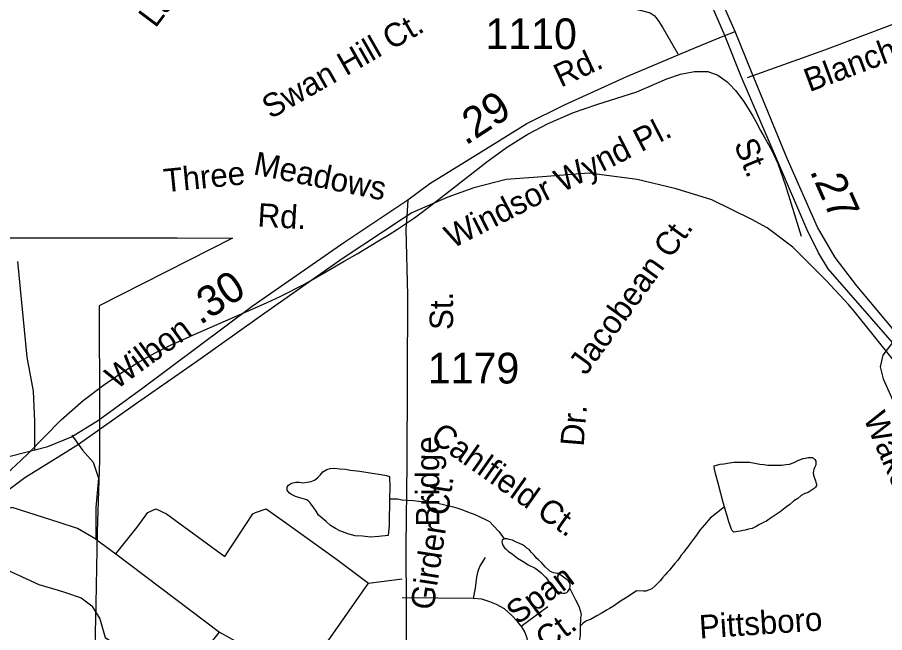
# Model space of a CAD drawing. Extents: x 2001466 to 2224147, y 644118 to 847247.
# Drawn here: x 2055654 to 2059179, y 671798 to 674300 of the extents above; entities that cross this region are included whole.
import ezdxf

# ---------------------------------------------------------------- set-up
doc = ezdxf.new("R2010")
doc.units = 0
for name, color, linetype in [('Exist Boundary Political City Limit New', 7, 'Continuous'), ('Exist Hydrographic Misc Water Feature', 7, 'Continuous'), ('Exist Railroad Mainline', 7, 'Continuous'), ('Exist Road Non-System Type 51', 7, 'Continuous'), ('Exist Road Non-System Type 51 Label', 7, 'Continuous'), ('Exist Road Primary NC Divided Attributed', 7, 'Continuous'), ('Exist Road Primary NC Label', 7, 'Continuous'), ('Exist Road Primary NC Service Mileage Hundredths English Label', 7, 'Continuous'), ('Exist Road Secondary Mileage Hundredths English Label', 7, 'Continuous'), ('Exist Road Secondary Type 51 Attributed', 7, 'Continuous'), ('Exist Road Secondary Type 51 Label', 7, 'Continuous'), ('Exist Road Secondary Type 51 Number Label', 7, 'Continuous'), ('Map Preparation Boundary City Limit Buffer Line', 7, 'Continuous')]:
    doc.layers.add(name, color=color, linetype=linetype)

msp = doc.modelspace()

# ---------------------------------------------------------------- linework, layer by layer
at = {"layer": 'Exist Boundary Political City Limit New'}
msp.add_lwpolyline([(2055624, 673403.6), (2055688.9, 673403.6), (2055823.9, 673403.5), (2055896.9, 673403.4), (2055968.9, 673403.4), (2056033.8, 673403.4), (2056108.6, 673403.3), (2056188.5, 673403.2), (2056303.8, 673403.2), (2056528.9, 673402.2), (2055987, 673126.9), (2055987.4, 672699.7), (2055987.5, 672626.9), (2055987.5, 672561.8), (2055987.6, 672500), (2055978.4, 672208.1), (2055972.6, 671915.2), (2055972.6, 671912.9), (2055959.8, 671338.6)], dxfattribs=at)
at = {"layer": 'Exist Hydrographic Misc Water Feature'}
for p, q in [((2057722.5, 673821.3), (2057728.6, 673824.6)), ((2057562.5, 673713), (2057577.3, 673723.6))]:
    msp.add_line(p, q, dxfattribs=at)
for points in [[(2058253.1, 674031.7), (2058293.5, 674049.2), (2058349.5, 674068.7), (2058406.7, 674080.3), (2058460.4, 674079), (2058501.5, 674064.7), (2058519.7, 674051.8)], [(2058253.1, 674031.7), (2058293.5, 674049.2), (2058349.5, 674068.7), (2058406.7, 674080.3), (2058460.4, 674079), (2058501.5, 674064.7), (2058519.7, 674051.8)], [(2057914.4, 673912.9), (2058008.5, 673945.7), (2058171.5, 673996.7), (2058253.1, 674031.7)], [(2057914.4, 673912.9), (2058008.5, 673945.7), (2058171.5, 673996.7), (2058253.1, 674031.7)], [(2058519.7, 674051.8), (2058538.6, 674038.3), (2058550.3, 674026.4)], [(2058519.7, 674051.8), (2058538.6, 674038.3), (2058550.3, 674026.4)], [(2058550.3, 674026.4), (2058573.4, 674002.1), (2058606.2, 673957.1)], [(2058550.3, 674026.4), (2058573.4, 674002.1), (2058606.2, 673957.1)], [(2058606.2, 673957.1), (2058643.6, 673897.5), (2058655, 673876.3)], [(2058606.2, 673957.1), (2058643.6, 673897.5), (2058655, 673876.3)], [(2057728.6, 673824.6), (2057811.5, 673868.1), (2057914.4, 673912.9)], [(2057728.6, 673824.6), (2057811.5, 673868.1), (2057914.4, 673912.9)], [(2058655, 673876.3), (2058674.3, 673840.2), (2058689.1, 673814)], [(2058655, 673876.3), (2058674.3, 673840.2), (2058689.1, 673814)], [(2057577.3, 673723.6), (2057642.5, 673770.2), (2057722.5, 673821.3)], [(2057577.3, 673723.6), (2057642.5, 673770.2), (2057722.5, 673821.3)], [(2058689.1, 673814), (2058718.6, 673761.2), (2058744.4, 673705), (2058775.6, 673616.3), (2058839.2, 673409.8)], [(2057164.9, 673417.6), (2057198.4, 673438.5), (2057267.5, 673485.2), (2057334.5, 673535.5), (2057562.5, 673713)], [(2057164.9, 673417.6), (2057198.4, 673438.5), (2057267.5, 673485.2), (2057334.5, 673535.5), (2057562.5, 673713)], [(2056982.8, 673308.3), (2057034.5, 673338.5), (2057121.5, 673390.6), (2057164.9, 673417.6)], [(2056982.8, 673308.3), (2057034.5, 673338.5), (2057121.5, 673390.6), (2057164.9, 673417.6)], [(2056820.4, 673215.6), (2056933.4, 673279.5), (2056982.8, 673308.3)], [(2056820.4, 673215.6), (2056933.4, 673279.5), (2056982.8, 673308.3)], [(2056669.1, 673140.7), (2056722.4, 673165.5), (2056820.4, 673215.6)], [(2056669.1, 673140.7), (2056722.4, 673165.5), (2056820.4, 673215.6)], [(2056310.3, 672982.5), (2056369.5, 673009.5), (2056630.6, 673122.7), (2056669.1, 673140.7)], [(2056310.3, 672982.5), (2056369.5, 673009.5), (2056630.6, 673122.7), (2056669.1, 673140.7)], [(2056078.6, 672855.5), (2056146.4, 672898.3), (2056213.5, 672935.6), (2056287.5, 672972.2), (2056310.3, 672982.5)], [(2056078.6, 672855.5), (2056146.4, 672898.3), (2056213.5, 672935.6), (2056287.5, 672972.2), (2056310.3, 672982.5)], [(2055921.5, 672741.5), (2056004.5, 672804.2), (2056078.6, 672855.5)], [(2055921.5, 672741.5), (2056004.5, 672804.2), (2056078.6, 672855.5)], [(2055669.1, 672499.2), (2055696.6, 672524.9), (2055831.5, 672664), (2055921.5, 672741.5)], [(2055669.1, 672499.2), (2055696.6, 672524.9), (2055831.5, 672664), (2055921.5, 672741.5)], [(2058528.1, 672309.2), (2058522, 672327.2), (2058503.9, 672401.2), (2058491.8, 672445.2), (2058487.7, 672463.1), (2058485.9, 672477.1), (2058509.9, 672483.2), (2058525.9, 672485.2), (2058547.8, 672489.2), (2058567.9, 672491.3), (2058587.8, 672491.3), (2058605.6, 672491.4), (2058629.6, 672491.4), (2058651.8, 672487.4), (2058671.9, 672483.5), (2058687.9, 672481.5), (2058703.8, 672479.5), (2058719.6, 672479.5), (2058741.8, 672479.6), (2058761.7, 672479.6), (2058777.7, 672481.7), (2058791.6, 672483.7), (2058811.7, 672489.7), (2058825.6, 672497.7), (2058847.6, 672505.8), (2058857.6, 672507.8), (2058867.7, 672509.8), (2058877.7, 672509.9), (2058883.7, 672509.9), (2058889.6, 672507.9), (2058895.8, 672501.9), (2058899.7, 672495.9), (2058899.7, 672483.9), (2058897.6, 672475.9), (2058893.7, 672467.8), (2058891.7, 672461.8), (2058889.8, 672455.9), (2058887.8, 672447.9), (2058889.8, 672437.9), (2058891.9, 672429.9), (2058897.8, 672415.9), (2058899.9, 672409.9), (2058901.7, 672401.9), (2058901.7, 672395.9), (2058898, 672389.9), (2058891.9, 672383.9), (2058880, 672375.9), (2058867.9, 672367.9), (2058853.9, 672363.8), (2058840, 672355.8), (2058825.9, 672343.8), (2058809.9, 672333.7), (2058794.1, 672319.7), (2058780.1, 672309.7), (2058768, 672299.7), (2058754.1, 672289.7), (2058734, 672275.6), (2058710.2, 672259.6), (2058698.1, 672251.6), (2058686.2, 672245.6), (2058670.2, 672237.5), (2058656.3, 672229.5), (2058640.3, 672221.5), (2058626.1, 672219.4), (2058612.4, 672215.4), (2058602.3, 672213.4), (2058592.3, 672211.4), (2058582.3, 672209.4), (2058566.3, 672207.3), (2058558.3, 672215.3), (2058546.2, 672249.3), (2058528.1, 672309.2)], [(2055558.1, 672412.4), (2055628.7, 672461.7), (2055669.1, 672499.2)], [(2055558.1, 672412.4), (2055628.7, 672461.7), (2055669.1, 672499.2)], [(2057166.4, 672342.7), (2057166.4, 672324.7), (2057164.5, 672258.7), (2057164.5, 672232.7), (2057162.5, 672208.7), (2057160.6, 672192.7), (2057122.5, 672188.7), (2057088.7, 672186.6), (2057056.7, 672190.5), (2057026.5, 672192.5), (2056996.6, 672200.4), (2056964.6, 672212.4), (2056946.6, 672222.3), (2056926.7, 672234.2), (2056908.6, 672250.3), (2056892.4, 672264.2), (2056878.5, 672276.2), (2056868.4, 672292.1), (2056858.4, 672306.2), (2056848.5, 672320.2), (2056844.4, 672326.1), (2056840.5, 672330.1), (2056830.5, 672338.1), (2056802.4, 672346), (2056784.4, 672352), (2056768.4, 672359.9), (2056760.4, 672365.9), (2056754.4, 672371.9), (2056750.3, 672377.9), (2056750.3, 672389.9), (2056756.3, 672397.9), (2056768.4, 672406), (2056786.4, 672410), (2056800.1, 672410), (2056814.3, 672408), (2056832.1, 672410.1), (2056848.1, 672412.1), (2056862.3, 672418.1), (2056874.2, 672428.1), (2056884.2, 672438.1), (2056896.1, 672452.2), (2056912.1, 672462.2), (2056926, 672466.2), (2056942, 672466.3), (2056964, 672464.3), (2056988.2, 672462.3), (2057008.1, 672458.4), (2057046, 672454.5), (2057096.2, 672446.6), (2057132.1, 672440.6), (2057154.3, 672436.6), (2057166.2, 672432.7), (2057166.2, 672428.7), (2057168.2, 672390.7), (2057166.4, 672342.7)], [(2057166.4, 672342.7), (2057198.4, 672342.8), (2057218.2, 672338.8), (2057238.3, 672336.8), (2057262.3, 672334.9), (2057286.3, 672332.9), (2057316.3, 672331), (2057336.4, 672327), (2057362.4, 672325.1), (2057386.4, 672319.1), (2057420.2, 672311.1), (2057440.3, 672305.2), (2057460.4, 672299.3), (2057490.3, 672287.3), (2057510.2, 672279.4), (2057534.2, 672269.4), (2057554.5, 672259.5), (2057572.4, 672249.5), (2057588.4, 672233.5)], [(2058528.1, 672309.2), (2058470.1, 672263.1), (2058446.1, 672237.1), (2058428.3, 672215.1), (2058414.3, 672195), (2058400.4, 672177), (2058388.5, 672161), (2058378.4, 672147), (2058370.4, 672137), (2058362.4, 672125), (2058352.4, 672112.9), (2058344.6, 672102.9), (2058338.6, 672092.9), (2058326.6, 672078.9), (2058314.5, 672064.9), (2058304.6, 672052.9), (2058294.8, 672042.9), (2058286.8, 672032.9), (2058276.7, 672020.9), (2058266.7, 672008.8), (2058256.6, 671998.8), (2058244.7, 671986.8), (2058232.8, 671976.7), (2058218.9, 671970.7), (2058208.9, 671966.7), (2058198.8, 671966.6), (2058170.7, 671968.6)], [(2057588.4, 672233.5), (2057612.4, 672207.5), (2057633.1, 672179.5)], [(2057633.1, 672179.5), (2057624.7, 672173.6), (2057622.6, 672167.6), (2057624.7, 672161.6), (2057626.5, 672153.6), (2057634.5, 672143.6), (2057640.7, 672137.6), (2057648.6, 672129.7), (2057666.5, 672117.7), (2057686.6, 672101.7), (2057702.8, 672091.7), (2057716.7, 672083.8), (2057730.7, 672073.8), (2057758.8, 672059.8), (2057768.6, 672053.8), (2057782.8, 672041.9), (2057792.8, 672031.9), (2057800.8, 672024), (2057808.8, 672014), (2057812.9, 672008), (2057818.8, 672000), (2057828.9, 671986), (2057832.8, 671978), (2057836.9, 671974), (2057844.9, 671968), (2057852.9, 671964), (2057860.9, 671960), (2057870.7, 671958.1), (2057878.7, 671958.1), (2057886.7, 671962.1), (2057890.8, 671966.1), (2057896.8, 671974.2), (2057898.8, 671978.2)], [(2057898.8, 671978.2), (2057900.9, 671986.2), (2057900.9, 671998.2), (2057892.9, 672010.1), (2057884.9, 672016.1), (2057868.7, 672028.1), (2057858.6, 672034.1), (2057850.6, 672038.1), (2057842.6, 672040.1), (2057832.6, 672042), (2057826.6, 672044), (2057818.6, 672048), (2057814.7, 672051.9), (2057798.7, 672065.9), (2057790.7, 672075.9), (2057784.6, 672083.9), (2057772.7, 672093.8), (2057764.7, 672099.8), (2057754.7, 672113.8), (2057742.6, 672125.9), (2057734.6, 672135.8), (2057724.5, 672141.8), (2057718.6, 672147.8), (2057706.5, 672155.7), (2057692.5, 672161.7), (2057678.6, 672167.7), (2057666.5, 672173.6), (2057652.5, 672177.6), (2057644.5, 672179.6), (2057633.1, 672179.5)], [(2057898.8, 671978.2), (2057910.7, 671956.1), (2057923, 671932.1), (2057931, 671916.2), (2057937, 671902.2), (2057940.8, 671888.2), (2057944.9, 671870.2), (2057943.1, 671860.2), (2057943.1, 671848.2), (2057941.1, 671830.2), (2057941.1, 671824.2)], [(2058170.7, 671968.6), (2058144.9, 671950.6), (2058118.8, 671934.6), (2058104.9, 671926.6), (2058077, 671906.5), (2058061, 671896.5), (2058051, 671890.4), (2058027, 671876.4), (2058009.1, 671866.4), (2057983.1, 671852.3), (2057967.1, 671846.3), (2057953.2, 671836.3), (2057941.1, 671824.2)], [(2057941.1, 671824.2), (2057941.1, 671818.2), (2057941.3, 671802.2), (2057941.3, 671786.2), (2057939.2, 671770.2), (2057939.2, 671758.2), (2057939.2, 671746.2), (2057937.4, 671732.2), (2057933.3, 671714.2), (2057929.4, 671692.2)]]:
    msp.add_lwpolyline(points, dxfattribs=at)
at = {"layer": 'Exist Railroad Mainline'}
for points in [[(2059031.5, 673131.8), (2058941.3, 673229.8), (2058805.2, 673365.8), (2058701.2, 673443.7), (2058639.3, 673477.8), (2058477.1, 673557.7), (2058332.2, 673602.5), (2058173.6, 673640.3), (2057977.2, 673666.8), (2057788.3, 673651.7), (2057641, 673640.3), (2057508.8, 673606.3), (2057403, 673568.5), (2057257.5, 673504.6), (2057218.2, 673479.1)], [(2057218.2, 673479.1), (2057137.5, 673426.7), (2056973.5, 673318.4), (2056636.3, 673081.1), (2056387, 672903.5), (2056137.7, 672729.7), (2055902.7, 672563.3), (2055892.2, 672555.8), (2055827.3, 672515.7), (2055684.4, 672427.4), (2055450.3, 672253.5), (2055321.8, 672170.4), (2055197.2, 672110), (2054951.7, 672019.3), (2054770.4, 671977.7), (2054593.3, 671966.4), (2054592.9, 671966.4), (2054219.7, 671991.7), (2054038.5, 672004), (2053746.7, 672011.7), (2053340.6, 672017.3), (2052916.7, 672031.1), (2052492.7, 672044.8), (2052327.8, 672061.8)], [(2059569.8, 672487.6), (2059215.5, 672905.9), (2059055.3, 673105.9), (2059031.5, 673131.8)]]:
    msp.add_lwpolyline(points, dxfattribs=at)
at = {"layer": 'Exist Road Non-System Type 51'}
for p, q in [((2055875.2, 672601.4), (2055902.7, 672563.3)), ((2055973.4, 672178.1), (2056054.4, 672118.6)), ((2056054.4, 672118.6), (2056475.6, 671799.9)), ((2057080.5, 671999.8), (2057218.1, 672016.5)), ((2057507.5, 671937.4), (2057218.1, 671939.8)), ((2057702.2, 671824.4), (2057810.4, 671903.9))]:
    msp.add_line(p, q, dxfattribs=at)
for points in [[(2057887.4, 674618.5), (2057919.3, 674566.6), (2057983.2, 674467.3), (2058008.5, 674430.8), (2058037.7, 674390.2), (2058055.3, 674369.8), (2058065.1, 674359.6), (2058090.8, 674345.1), (2058116.6, 674336.6), (2058152.6, 674335.8), (2058190.4, 674327.1), (2058226.2, 674318.4), (2058242, 674308), (2058249.8, 674297.9), (2058261.5, 674283.6), (2058277, 674257.3), (2058339, 674151.8)], [(2058621.6, 674055.9), (2058935.2, 674168), (2059209.2, 674270.4), (2059370.5, 674333.1), (2059584.1, 674412.8), (2059743.2, 674463.6), (2059879.9, 674498.8), (2060010.4, 674524.1), (2060062.5, 674531.1), (2060088.5, 674530.5), (2060116.3, 674520), (2060143.9, 674499.4), (2060149.7, 674487.3), (2060165.1, 674461), (2060174.3, 674422.8), (2060185.2, 674368.6), (2060210, 674306.1)], [(2055654.8, 673307.2), (2055692.6, 672918.2), (2055718.3, 672780.4), (2055723.7, 672656.2), (2055723.7, 672539.1)], [(2055902.7, 672563.3), (2055919.4, 672540), (2055962.6, 672491.4), (2055984.2, 672426.6), (2055973.4, 672307.7), (2055973.4, 672178.1)], [(2055823.4, 672245.6), (2055633.2, 672307.7), (2055600.8, 672296.9), (2055546.8, 672188.9), (2055525.2, 672102.4), (2055552.2, 672080.8), (2055741.2, 671994.4), (2055820, 671970.7)], [(2056054.4, 672118.6), (2056140.8, 672226.7), (2056184, 672286.1), (2056216.4, 672302.3), (2056259.6, 672280.7), (2056497.2, 672107.8), (2056610.6, 672280.7), (2056621.4, 672286.1), (2056664.6, 672302.3), (2056740.2, 672248.3), (2056950.9, 672097), (2057080.5, 671999.8)], [(2055973.4, 672178.1), (2055897.8, 672221.3), (2055823.4, 672245.6)], [(2057521.9, 672023.8), (2057526.2, 672048.8), (2057534, 672067.4), (2057556.6, 672103.3)], [(2057507.5, 671937.4), (2057516.1, 671979.4), (2057520, 672012.9), (2057521.9, 672023.8)], [(2056475.6, 671799.9), (2056632.2, 671713.5), (2056729.4, 671643.2), (2056761.8, 671616.2), (2056788.8, 671605.4), (2056832.1, 671643.2), (2057080.5, 671999.8)], [(2055820, 671970.7), (2055849.2, 671962), (2055914, 671940.4), (2055957.2, 671907.9), (2055989.6, 671853.9), (2056011.2, 671778.3), (2056119.2, 671708.1), (2056248.8, 671616.2), (2056292, 671616.2), (2056346, 671637.8), (2056475.6, 671799.9)], [(2057702.2, 671824.4), (2057686.6, 671843.9), (2057660.9, 671871.2), (2057634.5, 671894.5), (2057601.8, 671913.2), (2057574.5, 671924.1), (2057541.8, 671934.3), (2057507.5, 671937.4)], [(2057702.2, 671824.4), (2057716.2, 671799.5), (2057724.8, 671777.7), (2057744.7, 671600)]]:
    msp.add_lwpolyline(points, dxfattribs=at)
at = {"layer": 'Exist Road Primary NC Divided Attributed'}
for points in [[(2058571, 674242.1), (2058472.5, 674465.3), (2058355.8, 674721.4), (2058239.1, 674989.7), (2058183.1, 675136.2)], [(2058528.9, 674226), (2058444.1, 674423.4), (2058336.9, 674679.1), (2058220.3, 674947.4), (2058158.8, 675105.7)], [(2059239.5, 673001.2), (2059066.1, 673208.4), (2058977.4, 673322.8), (2058906.1, 673446.4), (2058782.6, 673725.5), (2058637.6, 674078.7), (2058571, 674242.1)], [(2059211.5, 672977.8), (2058950, 673278), (2058909.7, 673342.9), (2058863.1, 673439), (2058743.3, 673716.3), (2058595.4, 674058.9), (2058528.9, 674226)]]:
    msp.add_lwpolyline(points, dxfattribs=at)
at = {"layer": 'Exist Road Secondary Type 51 Attributed'}
for points in [[(2058528.9, 674226), (2058571, 674242.1)], [(2057241.4, 673558.1), (2057330.6, 673623.7), (2057538.6, 673753.6), (2057724.9, 673868.7), (2057877.9, 673943.7), (2058131.3, 674058.9), (2058407.9, 674175.7), (2058528.9, 674226)], [(2052319.8, 672269.5), (2052564.7, 672271.6), (2052923.6, 672258.9), (2053342.7, 672258.9), (2053707.9, 672252.6), (2054163.9, 672252.6), (2054428.3, 672261), (2054579.3, 672272.6), (2054749.2, 672302.2), (2055212.1, 672410), (2055539.3, 672494.5), (2055778.4, 672554.7), (2055874.5, 672594.8), (2055984.2, 672662.4), (2056163.7, 672793.4), (2056608.1, 673126.1), (2056984.4, 673387.1), (2057241.4, 673558.1)], [(2057241.4, 673558.1), (2057237, 673491.3), (2057233.5, 673438.8), (2057239.8, 673170.5), (2057236.7, 672486), (2057232.4, 672150.1), (2057235.6, 671636.7), (2057227.2, 671579.7), (2057176.5, 671535.3), (2057070.9, 671533.2), (2056973.8, 671539.5), (2056906.3, 671526.9), (2056868.3, 671493.1), (2056855.6, 671427.6), (2056859.8, 671159.3), (2056852.4, 670779), (2056852.4, 670487.4), (2056840.8, 669788.2), (2056856.8, 669540.5), (2056871.5, 669321.9), (2056884.7, 669250.8), (2056903.7, 669186.3), (2056949.2, 669074.8), (2056997.6, 668963.3)], [(2059131.8, 673024.2), (2059131.8, 673024.2)], [(2059211.5, 672977.8), (2059172, 672926.4), (2059161, 672879), (2059172.5, 672830.1), (2059202.6, 672764), (2059297.9, 672543.6), (2059378.4, 672372.5), (2059440.7, 672274.7), (2059580, 672061.4), (2059639.1, 671951.5), (2059694, 671801.5), (2059828.1, 671391.7), (2059851.3, 671245.9), (2059857.6, 671104.3), (2059846.2, 670949.9), (2059798, 670719.9), (2059731.4, 670393.6)]]:
    msp.add_lwpolyline(points, dxfattribs=at)
at = {"layer": 'Map Preparation Boundary City Limit Buffer Line'}
msp.add_lwpolyline([(2055624, 673403.6), (2055688.9, 673403.6), (2055823.9, 673403.5), (2055896.9, 673403.4), (2055968.9, 673403.4), (2056033.8, 673403.4), (2056108.6, 673403.3), (2056188.5, 673403.2), (2056303.8, 673403.2), (2056528.9, 673402.2), (2055987, 673126.9), (2055987.4, 672699.7), (2055987.5, 672626.9), (2055987.5, 672561.8), (2055987.6, 672500), (2055978.4, 672208.1), (2055972.6, 671915.2), (2055972.6, 671912.9), (2055959.8, 671338.6)], dxfattribs=at)

# ---------------------------------------------------------------- texts
at = {"layer": 'Exist Road Non-System Type 51 Label'}
for s, rotation, p in [('Laverton Ct.', 53.0975, (2056215, 674253.3)), ('Swan Hill Ct.', 29.7761, (2056683.2, 673884.5)), ('Blanchard', 20.4924, (2058873.3, 673995.3)), ('Windsor Wynd Pl.', 27.1015, (2057422.2, 673358.3)), ('Meadows', 348.6492, (2056609.2, 673661.9)), ('Three', 5.7177, (2056253, 673588.3)), ('Rd.', 356.6292, (2056628.4, 673449.8)), ('Jacobean Ct.', 54.0071, (2057964.8, 672840.7)), ('Dr.', 85.2981, (2057955.4, 672553.2)), ('Cahlfield Ct.', 324.852, (2057326.8, 672581.7)), ('Girder Ct.', 81.2827, (2057344.7, 671886.5)), ('Span ', 36.2775, (2057686, 671827.5)), ('Pittsboro', 3.8378, (2058427.9, 671774.2)), ('Ct.', 36.2775, (2057804.6, 671720.7))]:
    msp.add_text(s, height=95, rotation=rotation, dxfattribs=at).set_placement(p)
at = {"layer": 'Exist Road Primary NC Label'}
msp.add_text(' St.', height=95, rotation=292.4566, dxfattribs=at).set_placement((2058551.2, 673817.5))
at = {"layer": 'Exist Road Primary NC Service Mileage Hundredths English Label'}
msp.add_text('.27', height=125, rotation=293.8642, dxfattribs=at).set_placement((2058873.3, 673675))
at = {"layer": 'Exist Road Secondary Mileage Hundredths English Label'}
for s, rotation, p in [('.29', 33.0848, (2057475.7, 673777)), ('.30', 33.1422, (2056396.8, 673046.9))]:
    msp.add_text(s, height=125, rotation=rotation, dxfattribs=at).set_placement(p)
at = {"layer": 'Exist Road Secondary Type 51 Label'}
for s, rotation, p in [('Rd.', 25.0867, (2057862.5, 674013.6)), (' St.', 89.9956, (2057424.7, 672993.6)), ('Wilbon', 36.1824, (2056056.3, 672783.9)), ('Wake', 293.3262, (2059091, 672671.4)), ('Bridge', 89.9956, (2057368.8, 672229.1))]:
    msp.add_text(s, height=95, rotation=rotation, dxfattribs=at).set_placement(p)
at = {"layer": 'Exist Road Secondary Type 51 Number Label'}
for s, p in [('1110', (2057556.3, 674170.5)), ('1179', (2057322.1, 672811.2))]:
    msp.add_text(s, height=125, dxfattribs=at).set_placement(p)

doc.saveas('drawing.dxf')
